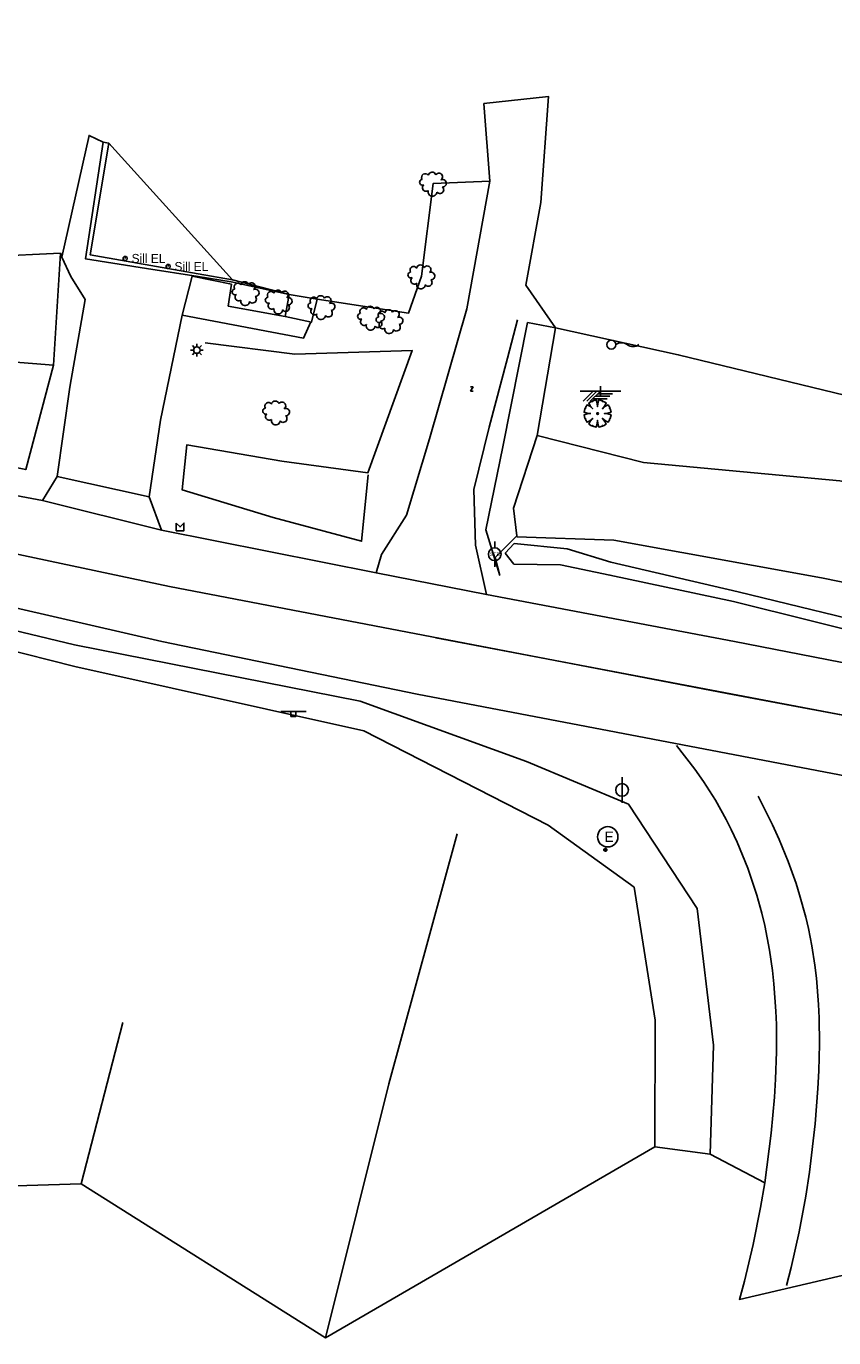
# Model space of a CAD drawing. Extents: x 1158469 to 1165378, y 609843 to 611748.
# Drawn here: x 1160112.7 to 1160271, y 610963 to 611220.3 of the extents above; entities that cross this region are included whole.
import ezdxf

# ---------------------------------------------------------------- set-up
doc = ezdxf.new("R2010")
doc.units = 0
for name, color, linetype in [('Exterior Boundary', 7, 'Continuous'), ('S_Buildings', 7, 'Continuous'), ('S_Buildings_SillElevation', 7, 'Continuous'), ('S_Ground_Elevation', 7, 'Continuous'), ('S_Ground_LevelString', 7, 'Continuous'), ('S_Ground_SpotElevation', 7, 'Continuous'), ('S_Misc_MiscItems', 7, 'Continuous'), ('S_Property_FlagPole', 7, 'Continuous'), ('S_Property_Light', 7, 'Continuous'), ('S_Property_Mailbox', 7, 'Continuous'), ('S_Property_Walkways', 7, 'Continuous'), ('S_Roadway_Centerline', 7, 'Continuous'), ('S_Roadway_Drive_Paved', 7, 'Continuous'), ('S_Roadway_Edge_Pavement', 7, 'Continuous'), ('S_Roadway_Edge_TW', 7, 'Continuous'), ('S_Roadway_Ledge_Single_Shot', 7, 'Continuous'), ('S_Traffic_Sign_SinglePost', 7, 'Continuous'), ('S_Trees_Bush', 7, 'Continuous'), ('S_Trees_Decid_NonPay', 7, 'Continuous'), ('S_Utilities_Pole_Power', 7, 'Continuous'), ('S_Utilities_Pole_Stub', 7, 'Continuous'), ('S_Utilities_UG_Electrical_MH', 7, 'Continuous')]:
    doc.layers.add(name, color=color, linetype=linetype)

msp = doc.modelspace()

# ---------------------------------------------------------------- linework, layer by layer
at = {"layer": 'Exterior Boundary'}
for points in [[(1160275.51, 611147.29), (1160240.5, 611155.81), (1160216.47, 611161.11), (1160210.64, 611169.49), (1160213.56, 611185.68), (1160215.1, 611206.46), (1160202.4, 611205.11), (1160203.56, 611189.85), (1160192.43, 611189.41), (1160190.15, 611171.22), (1160187.64, 611164), (1160169.72, 611166.73), (1160164.24, 611167.67), (1160153.12, 611170.55), (1160146.37, 611171.72), (1160125.2, 611175.41), (1160128.82, 611197.36), (1160127.76, 611197.51), (1160124.98, 611198.84), (1160119.62, 611174.99), (1160119.36, 611175.73), (1160092, 611174.42)], [(1160040.38, 610990.61), (1160123.4, 610993.21), (1160171.36, 610962.98), (1160235.89, 611000.42), (1160246.76, 610998.98), (1160257.47, 610993.36), (1160256.67, 610988.52), (1160255.23, 610981.3), (1160253.49, 610974.1), (1160252.49, 610970.51), (1160276.84, 610976.17), (1160300.13, 610980.39), (1160300.34, 610984.68), (1160300.59, 610987.5), (1160301.32, 610993.01), (1160316.27, 610990.83), (1160322.81, 610989.73), (1160383.99, 610973.48), (1160427.63, 610966.67)]]:
    msp.add_lwpolyline(points, dxfattribs=at)
at = {"layer": 'S_Buildings'}
msp.add_lwpolyline([(1160128.82, 611197.36), (1160125.2, 611175.41), (1160146.37, 611171.72), (1160153.12, 611170.55)], close=True, dxfattribs=at)
at = {"layer": 'S_Buildings_SillElevation'}
for p, q in [((1160132.04, 611174.72), (1160132.04, 611175.12)), ((1160140.46, 611173.15), (1160140.46, 611173.54))]:
    msp.add_line(p, q, dxfattribs=at)
for points in [[(1160132.44, 611174.88), (1160132.21, 611175.12), (1160131.88, 611175.12), (1160131.65, 611174.88), (1160131.65, 611174.56), (1160131.88, 611174.33), (1160132.21, 611174.33), (1160132.44, 611174.56)], [(1160140.85, 611173.31), (1160140.62, 611173.54), (1160140.29, 611173.54), (1160140.06, 611173.31), (1160140.06, 611172.98), (1160140.29, 611172.75), (1160140.62, 611172.75), (1160140.85, 611172.98)]]:
    msp.add_lwpolyline(points, close=True, dxfattribs=at)
at = {"layer": 'S_Ground_Elevation'}
for points in [[(1160119.36, 611175.73), (1160118.03, 611153.8), (1160112.56, 611133.3), (1160089.95, 611137.83), (1160063.24, 611142.61), (1160044.4, 611147.63), (1160033.61, 611155.48), (1160025.45, 611175.25), (1160028.08, 611191.17), (1160066.13, 611182.04), (1160092, 611174.42)], [(1160205.54, 611112.53), (1160202.77, 611121.47), (1160206.13, 611137.76), (1160210.97, 611162.15), (1160216.47, 611161.11), (1160212.83, 611139.96), (1160208.22, 611125.7), (1160208.88, 611120.3), (1160204.59, 611116.05)]]:
    msp.add_lwpolyline(points, close=True, dxfattribs=at)
for points in [[(1160203.56, 611189.85), (1160192.43, 611189.41), (1160190.15, 611171.22), (1160187.64, 611164), (1160169.72, 611166.73), (1160164.24, 611167.67), (1160152.82, 611170.15)], [(1160118.03, 611153.8), (1160093.2, 611155.73), (1160068.22, 611162.76), (1160049.43, 611166.66), (1160025.45, 611175.25)], [(1160169.72, 611166.73), (1160168.6, 611162.24), (1160163.42, 611163.33), (1160164.24, 611167.67)], [(1160216.47, 611161.11), (1160240.5, 611155.81), (1160275.51, 611147.29), (1160328.64, 611134.2), (1160353.39, 611134.87), (1160360.34, 611134.25), (1160372.35, 611131.62)], [(1160147.73, 611158.16), (1160165.3, 611155.95), (1160188.35, 611156.63), (1160179.66, 611132.66), (1160162.78, 611134.92), (1160144.14, 611138.13), (1160143.21, 611129.33), (1160161.06, 611123.89), (1160178.42, 611119.25), (1160179.7, 611132.24)], [(1160212.83, 611139.96), (1160233.7, 611134.71), (1160272.21, 611131.06), (1160323.91, 611120.37), (1160348, 611118.67), (1160353.99, 611117.12), (1160371.58, 611117.08)], [(1160178.15, 611087.84), (1160122.12, 611098.94), (1160072.33, 611110.86), (1160023.52, 611120.14), (1159999.09, 611125.43), (1159964.23, 611129.8)], [(1160387.92, 611095.8), (1160358.54, 611092.48), (1160335.66, 611093.44), (1160310.22, 611097.06), (1160283.45, 611101.75), (1160252.25, 611109.34), (1160227.29, 611115.16), (1160218.71, 611117.72), (1160208.31, 611118.79), (1160206.59, 611116.91)], [(1160208.88, 611120.11), (1160227.89, 611119.43), (1160268.61, 611112.05), (1160313.76, 611102.85), (1160319.59, 611101.32), (1160328.13, 611100.36), (1160341.96, 611098.72), (1160348.43, 611098.21), (1160348.39, 611098.22), (1160370.91, 611096.32)], [(1160178.85, 611082.06), (1160122.16, 611094.69), (1160107.75, 611098.32), (1160087.68, 611104.14), (1160071.8, 611106.45), (1160017.91, 611115.36), (1159998.23, 611117.43)], [(1160388.97, 611092.56), (1160358.47, 611089.42), (1160335.45, 611090.34), (1160309.87, 611094.37), (1160282.6, 611099.62), (1160251.34, 611107.41), (1160227.1, 611112.6), (1160217.45, 611114.61), (1160208.3, 611114.72), (1160206.59, 611116.91)], [(1160178.15, 611087.84), (1160210.75, 611076.01)], [(1160178.85, 611082.06), (1160215.02, 611063.57)], [(1160210.75, 611076.01), (1160230.74, 611067.69), (1160244.23, 611047.21), (1160247.43, 611020.39), (1160246.76, 610998.98)], [(1160171.36, 610962.98), (1160183.78, 611012.78), (1160197.16, 611061.85)], [(1160235.89, 611000.42), (1160235.96, 611025.32), (1160231.87, 611051.37), (1160215.02, 611063.57)], [(1160123.4, 610993.21), (1160131.61, 611024.8)]]:
    msp.add_lwpolyline(points, dxfattribs=at)
at = {"layer": 'S_Ground_LevelString'}
for points in [[(1160152.82, 611170.15), (1160146.38, 611171.19), (1160136.24, 611172.72), (1160124.29, 611174.62), (1160127.76, 611197.51), (1160124.98, 611198.84)], [(1160118.72, 611131.93), (1160136.76, 611127.95)]]:
    msp.add_lwpolyline(points, dxfattribs=at)
at = {"layer": 'S_Ground_SpotElevation'}
for p, q in [((1160200.29, 611149.5), (1160199.76, 611148.71)), ((1160199.77, 611149.5), (1160200.29, 611149.5)), ((1160199.87, 611149.11), (1160200.18, 611149.11)), ((1160199.76, 611148.71), (1160200.29, 611148.71))]:
    msp.add_line(p, q, dxfattribs=at)
at = {"layer": 'S_Misc_MiscItems'}
for p, q in [((1160226.22, 611059.09), (1160226.22, 611058.3)), ((1160226.61, 611058.7), (1160225.82, 611058.7)), ((1160226.48, 611058.43), (1160225.95, 611058.96)), ((1160226.48, 611058.96), (1160225.95, 611058.43))]:
    msp.add_line(p, q, dxfattribs=at)
at = {"layer": 'S_Property_FlagPole'}
msp.add_circle((1160227.39, 611157.81), 0.875, dxfattribs=at)
for centre, start, end in [((1160229.39, 611156.31), 53.1301, 126.8699), ((1160231.64, 611159.31), 233.1301, 306.8699)]:
    msp.add_arc(centre, 1.88, start, end, dxfattribs=at)
at = {"layer": 'S_Property_Light'}
for p, q in [((1160145.67, 611157.17), (1160145.23, 611157.61)), ((1160146.11, 611157.35), (1160146.11, 611157.98)), ((1160146.55, 611157.17), (1160146.99, 611157.61)), ((1160145.48, 611156.73), (1160144.86, 611156.73)), ((1160145.67, 611156.28), (1160145.23, 611155.84)), ((1160146.11, 611156.1), (1160146.11, 611155.48)), ((1160146.55, 611156.28), (1160146.99, 611155.84)), ((1160146.73, 611156.73), (1160147.36, 611156.73))]:
    msp.add_line(p, q, dxfattribs=at)
msp.add_circle((1160146.11, 611156.73), 0.625, dxfattribs=at)
at = {"layer": 'S_Property_Mailbox'}
msp.add_lwpolyline([(1160142.08, 611122.81), (1160142.08, 611121.31), (1160143.58, 611121.31), (1160143.58, 611122.81), (1160142.83, 611122.06)], close=True, dxfattribs=at)
at = {"layer": 'S_Property_Walkways'}
for points in [[(1160168.6, 611162.24), (1160163.42, 611163.33), (1160152.27, 611165.37), (1160152.9, 611169.67), (1160145.17, 611171.27)], [(1160143.24, 611163.58), (1160167, 611159.06), (1160168.43, 611162.25)]]:
    msp.add_lwpolyline(points, dxfattribs=at)
at = {"layer": 'S_Roadway_Centerline'}
for points in [[(1159674.4, 611208.15), (1159724.52, 611197.44), (1159772.65, 611187.93), (1159824.57, 611177.42), (1159874.43, 611167.91), (1159923.93, 611157.09), (1159972.8, 611146.67), (1160026.16, 611134.7), (1160140.76, 611110.36), (1160250.08, 611089.38), (1160351.64, 611070.35), (1160400.84, 611060.03)], [(1160192.96, 611100.27), (1160301.07, 611079.73)]]:
    msp.add_lwpolyline(points, dxfattribs=at)
at = {"layer": 'S_Roadway_Drive_Paved'}
for points in [[(1160182.32, 611116.64), (1160187.25, 611124.36), (1160191.74, 611139.3), (1160199.04, 611164.85), (1160203.56, 611189.85), (1160202.4, 611205.11), (1160215.1, 611206.46), (1160213.56, 611185.68), (1160210.64, 611169.49)], [(1160124.98, 611198.84), (1160119.62, 611174.99), (1160121.42, 611171.17), (1160124.23, 611166.65), (1160121.19, 611149.45), (1160118.72, 611131.93)], [(1160136.76, 611127.95), (1160138.98, 611142.97), (1160143.24, 611163.58), (1160145.17, 611171.27)], [(1160200.72, 611118.5), (1160200.44, 611129.41), (1160203.44, 611141.61), (1160207.06, 611155.13), (1160209, 611162.69)], [(1160118.72, 611131.93), (1160115.81, 611127.25)], [(1160136.76, 611127.95), (1160139.19, 611121.39)], [(1160200.72, 611118.5), (1160202.93, 611108.8)], [(1160182.32, 611116.64), (1160181.25, 611113.06)]]:
    msp.add_lwpolyline(points, dxfattribs=at)
at = {"layer": 'S_Roadway_Edge_Pavement'}
for points in [[(1159674.19, 611220.27), (1159727.62, 611208.45), (1159775.2, 611198.63), (1159828.01, 611187.77), (1159875.81, 611178.05), (1159927.48, 611167.26), (1159973.95, 611157.61), (1159983.55, 611155.65), (1160032.97, 611144.6), (1160085.1, 611132.97), (1160115.81, 611127.25), (1160139.19, 611121.39), (1160181.25, 611113.06), (1160202.93, 611108.8), (1160251.54, 611099.55), (1160303.52, 611089.42), (1160352.24, 611080.23), (1160375.58, 611075.72), (1160418.32, 611067.56)], [(1159672.36, 611195.55), (1159721.94, 611187.24), (1159771.19, 611177.73), (1159821.35, 611166.96), (1159873.21, 611157.01), (1159921.1, 611146.52), (1159969.11, 611136.9), (1160022.87, 611124.94), (1160082.61, 611112.56), (1160139.27, 611099.57), (1160189.32, 611089.24), (1160248.51, 611077.95), (1160297.09, 611068.63), (1160349.46, 611058.61), (1160397, 611049.16)], [(1160252.49, 610970.51), (1160253.49, 610974.1), (1160255.23, 610981.3), (1160256.67, 610988.52), (1160257.47, 610993.36), (1160258.73, 611003.1), (1160259.37, 611010.18), (1160259.59, 611013.74), (1160259.77, 611019.08), (1160259.75, 611024.42), (1160259.66, 611027.08), (1160259.28, 611032.4), (1160258.99, 611035.05), (1160258.41, 611039.02), (1160257.47, 611043.86), (1160256.89, 611046.26), (1160255.91, 611049.83), (1160254.16, 611055.09), (1160252.07, 611060.21), (1160250.9, 611062.7), (1160249.92, 611064.64), (1160247.79, 611068.44), (1160245.46, 611072.12), (1160243.78, 611074.52), (1160240.16, 611079.19)]]:
    msp.add_lwpolyline(points, dxfattribs=at)
at = {"layer": 'S_Roadway_Edge_TW'}
msp.add_lwpolyline([(1160261.72, 610973.27), (1160262.64, 610976.76), (1160264.24, 610983.76), (1160265.54, 610990.78), (1160266.26, 610995.48), (1160267.36, 611004.96), (1160267.91, 611011.88), (1160268.09, 611015.36), (1160268.22, 611020.57), (1160268.14, 611025.77), (1160268.03, 611028.36), (1160267.61, 611033.52), (1160267.3, 611036.08), (1160266.71, 611039.89), (1160266.04, 611043.26), (1160265.52, 611045.48), (1160264.3, 611049.9), (1160263.61, 611052.09), (1160262.06, 611056.44), (1160260.3, 611060.75), (1160259.02, 611063.6), (1160256.18, 611069.25)], dxfattribs=at)
at = {"layer": 'S_Roadway_Ledge_Single_Shot'}
for p, q in [((1160225.27, 611149.69), (1160225.27, 611147.69)), ((1160221.27, 611148.69), (1160229.27, 611148.69)), ((1160223.85, 611148.69), (1160221.85, 611146.69)), ((1160224.56, 611148.69), (1160222.56, 611146.69)), ((1160225.27, 611148.69), (1160223.27, 611146.69)), ((1160226.6, 611147.19), (1160223.77, 611147.19)), ((1160227.1, 611147.69), (1160224.27, 611147.69)), ((1160227.6, 611148.19), (1160224.77, 611148.19))]:
    msp.add_line(p, q, dxfattribs=at)
at = {"layer": 'S_Traffic_Sign_SinglePost'}
msp.add_line((1160162.55, 611085.86), (1160167.55, 611085.86), dxfattribs=at)
msp.add_lwpolyline([(1160164.55, 611085.86), (1160165.55, 611085.86), (1160165.55, 611084.86), (1160164.55, 611084.86)], close=True, dxfattribs=at)
at = {"layer": 'S_Trees_Bush'}
for centre, radius, start, end in [((1160190.36, 611189.66), 0.576, 95.1875, 295.4615), ((1160190.9, 611190.63), 0.717, 33.6405, 213.5909), ((1160192.26, 611190.86), 0.776, 19.7277, 168.0032), ((1160193.57, 611190.72), 0.715, 304.7168, 145.2832), ((1160194.3, 611189.47), 0.733, 268.122, 116.0172), ((1160191.05, 611188.59), 0.706, 129.1555, 309.4105), ((1160192.33, 611187.8), 0.862, 163.7427, 356.276), ((1160193.78, 611188.19), 0.742, 216.9809, 47.4965), ((1160188.62, 611172.44), 0.717, 33.6405, 213.5909), ((1160189.98, 611172.68), 0.776, 19.7277, 168.0032), ((1160191.3, 611172.53), 0.715, 304.7168, 145.2832), ((1160154.16, 611169.14), 0.717, 33.6405, 213.5909), ((1160155.52, 611169.38), 0.776, 19.7277, 168.0032), ((1160156.84, 611169.23), 0.715, 304.7168, 145.2832), ((1160188.08, 611171.47), 0.576, 95.1875, 295.4615), ((1160188.77, 611170.4), 0.706, 129.1555, 309.4105), ((1160190.05, 611169.61), 0.862, 163.7427, 356.276), ((1160191.5, 611170), 0.742, 216.9809, 47.4965), ((1160192.03, 611171.28), 0.733, 268.122, 116.0172), ((1160153.62, 611168.17), 0.576, 95.1875, 295.4615), ((1160154.31, 611167.1), 0.706, 129.1555, 309.4105), ((1160157.04, 611166.71), 0.742, 216.9809, 47.4965), ((1160157.57, 611167.99), 0.733, 268.122, 116.0172), ((1160160.1, 611166.54), 0.576, 95.1875, 295.4615), ((1160160.64, 611167.51), 0.717, 33.6405, 213.5909), ((1160162, 611167.74), 0.776, 19.7277, 168.0032), ((1160163.32, 611167.6), 0.715, 304.7168, 145.2832), ((1160164.05, 611166.35), 0.733, 268.122, 116.0172), ((1160169.04, 611166.4), 0.717, 33.6405, 213.5909), ((1160170.39, 611166.64), 0.776, 19.7277, 168.0032), ((1160171.71, 611166.49), 0.715, 304.7168, 145.2832), ((1160155.59, 611166.32), 0.862, 163.7427, 356.276), ((1160160.79, 611165.47), 0.706, 129.1555, 309.4105), ((1160162.07, 611164.68), 0.862, 163.7427, 356.276), ((1160163.52, 611165.07), 0.742, 216.9809, 47.4965), ((1160168.49, 611165.43), 0.576, 95.1875, 295.4615), ((1160169.19, 611164.36), 0.706, 129.1555, 309.4105), ((1160171.92, 611163.97), 0.742, 216.9809, 47.4965), ((1160172.44, 611165.25), 0.733, 268.122, 116.0172), ((1160178.77, 611164.33), 0.717, 33.6405, 213.5909), ((1160180.12, 611164.56), 0.776, 19.7277, 168.0032), ((1160181.44, 611164.42), 0.715, 304.7168, 145.2832), ((1160183.74, 611163.89), 0.776, 19.7277, 168.0032), ((1160185.06, 611163.75), 0.715, 304.7168, 145.2832), ((1160170.46, 611163.58), 0.862, 163.7427, 356.276), ((1160178.22, 611163.36), 0.576, 95.1875, 295.4615), ((1160178.92, 611162.29), 0.706, 129.1555, 309.4105), ((1160181.65, 611161.89), 0.742, 216.9809, 47.4965), ((1160181.84, 611162.69), 0.576, 95.1875, 295.4615), ((1160182.39, 611163.66), 0.717, 33.6405, 213.5909), ((1160182.54, 611161.62), 0.706, 129.1555, 309.4105), ((1160182.17, 611163.17), 0.733, 268.122, 116.0172), ((1160185.79, 611162.5), 0.733, 268.122, 116.0172), ((1160180.19, 611161.5), 0.862, 163.7427, 356.276), ((1160183.81, 611160.83), 0.862, 163.7427, 356.276), ((1160185.26, 611161.22), 0.742, 216.9809, 47.4965), ((1160160.15, 611145.74), 0.717, 33.6405, 213.5909), ((1160161.51, 611145.97), 0.776, 19.7277, 168.0032), ((1160162.82, 611145.83), 0.715, 304.7168, 145.2832), ((1160159.61, 611144.77), 0.576, 95.1875, 295.4615), ((1160160.3, 611143.7), 0.706, 129.1555, 309.4105), ((1160163.55, 611144.58), 0.733, 268.122, 116.0172), ((1160161.58, 611142.91), 0.862, 163.7427, 356.276), ((1160163.03, 611143.3), 0.742, 216.9809, 47.4965)]:
    msp.add_arc(centre, radius, start, end, dxfattribs=at)
at = {"layer": 'S_Trees_Decid_NonPay'}
msp.add_lwpolyline([(1160223.36, 611144.29), (1160222.67, 611144.34), (1160222.03, 611144.55), (1160222.19, 611145.24), (1160222.35, 611145.24), (1160222.3, 611145.46), (1160222.62, 611145.99), (1160223.15, 611145.72), (1160223.73, 611145.24), (1160223.25, 611145.83), (1160222.99, 611146.36), (1160223.52, 611146.68), (1160223.73, 611146.63), (1160223.73, 611146.79), (1160224.42, 611146.95), (1160224.64, 611146.31), (1160224.69, 611145.62), (1160224.74, 611146.31), (1160224.96, 611146.95), (1160225.65, 611146.79), (1160225.65, 611146.63), (1160225.86, 611146.68), (1160226.39, 611146.36), (1160226.12, 611145.83), (1160225.65, 611145.24), (1160226.23, 611145.72), (1160226.76, 611145.99), (1160227.08, 611145.46), (1160227.03, 611145.24), (1160227.19, 611145.24), (1160227.35, 611144.55), (1160226.71, 611144.34), (1160226.02, 611144.29), (1160226.71, 611144.23), (1160227.35, 611144.02), (1160227.19, 611143.33), (1160227.03, 611143.33), (1160227.08, 611143.12), (1160226.76, 611142.59), (1160226.23, 611142.85), (1160225.65, 611143.33), (1160226.12, 611142.75), (1160226.39, 611142.22), (1160225.86, 611141.9), (1160225.65, 611141.95), (1160225.65, 611141.79), (1160224.96, 611141.63), (1160224.74, 611142.27), (1160224.69, 611142.96), (1160224.64, 611142.27), (1160224.42, 611141.63), (1160223.73, 611141.79), (1160223.73, 611141.95), (1160223.52, 611141.9), (1160222.99, 611142.22), (1160223.25, 611142.75), (1160223.73, 611143.33), (1160223.15, 611142.85), (1160222.62, 611142.59), (1160222.3, 611143.12), (1160222.35, 611143.33), (1160222.19, 611143.33), (1160222.03, 611144.02), (1160222.67, 611144.23), (1160223.36, 611144.29)], dxfattribs=at)
msp.add_circle((1160224.69, 611144.29), 0.167, dxfattribs=at)
at = {"layer": 'S_Utilities_Pole_Power'}
msp.add_line((1160229.49, 611072.95), (1160229.49, 611067.95), dxfattribs=at)
msp.add_circle((1160229.49, 611070.45), 1.25, dxfattribs=at)
at = {"layer": 'S_Utilities_Pole_Stub'}
for p, q in [((1160204.53, 611119.2), (1160204.53, 611117.95)), ((1160204.53, 611115.45), (1160204.53, 611114.2))]:
    msp.add_line(p, q, dxfattribs=at)
msp.add_circle((1160204.53, 611116.7), 1.25, dxfattribs=at)
at = {"layer": 'S_Utilities_UG_Electrical_MH'}
msp.add_circle((1160226.69, 611061.26), 2, dxfattribs=at)

# ---------------------------------------------------------------- texts
at = {"layer": 'S_Buildings_SillElevation'}
for p in [(1160133.31, 611173.85), (1160141.72, 611172.27)]:
    msp.add_text('Sill EL', height=1.75, dxfattribs=at).set_placement(p)
at = {"layer": 'S_Utilities_Pole_Stub'}
msp.add_text('STB', height=0.75, dxfattribs=at).set_placement((1160203.55, 611116.33))
at = {"layer": 'S_Utilities_UG_Electrical_MH'}
msp.add_text('E', height=2, dxfattribs=at).set_placement((1160226.07, 611060.26))

doc.saveas('drawing.dxf')
